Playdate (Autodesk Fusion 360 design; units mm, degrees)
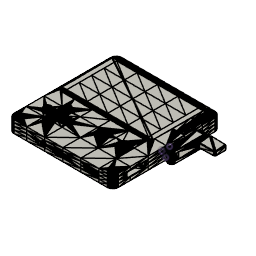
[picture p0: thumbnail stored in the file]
description: Part Number
part number: product0
base_feature "Base Feature1" bodies "Crank wBase", "USB Tab", "Btn Menu", "USB Tab 2", "USB Tab 3", "Cover Mount BR", "Cover Mount BL", "Crank Paddle Hinge"
scale "Scale1" ScaleFactor 1009.706
work_plane "WorkPlane1" AlongDistance 0
work_plane "WorkPlane2" AlongDistance 0
component_from_bodies "Body->Comp"
copy_paste_bodies "CopyPasteBodies1"
move "Move1"
copy_paste_bodies "CopyPasteBodies1"
move "Move1"
copy_paste_bodies "CutPasteBodies1"
copy_paste_bodies "CopyPasteBodies2"
move "Move2"
box_primitive "BoxPrimitive1" DistanceX 27.922 DistanceY 5.467 DistanceZ 5 OffsetDistanceX 0 OffsetDistanceY 0
box_primitive "BoxPrimitive2" DistanceX 27.931 DistanceY 5.556 DistanceZ 6 OffsetDistanceX 0 OffsetDistanceY 0 bodies "Hinge"
box_primitive "BoxPrimitive3" DistanceX 5.517 DistanceY 5.897 DistanceZ 4.5001 OffsetDistanceX 0 OffsetDistanceY 0 bodies "Crank Body"
work_plane "WorkPlane1" AlongDistance 0
sketch "Roll Hinge" plane through (0, 0, -0.4069) normal (0, 0, 1) x axis (1, 0, 0)
  circle C1 centre (44.8638, -16.7129) radius 0.8787
  point P2 (45.5747, -17.2294)
  point P3 (44.1529, -17.2294)
  point P4 (44.5923, -15.8772)
  coincident P2 C1
  coincident P3 C1
  coincident P4 C1
work_axis "WorkAxis1" sketch "Roll Hinge"
work_plane "WorkPlane2" AlongDistance 0
sketch "Tilt Hinge" plane through (40.6438, 0, 0) normal (-1, 0, 0) x axis (0, -1, 0)
  circle C1 centre (16.7129, -4.4318) radius 3.4401
  point P2 (13.9298, -2.4097)
  point P3 (19.496, -2.4097)
  point P4 (16.7129, -7.8718)
  coincident P2 C1
  coincident P3 C1
  coincident P4 C1
work_axis "WorkAxis2" sketch "Tilt Hinge"
move "Move3" RotateAngle 180
copy_paste_bodies "CutPasteBodies1"
copy_paste_bodies "CutPasteBodies1"
extrude "Extrude1" sketch "Roll Hinge" blind 0.1 bodies "ASSY Joint"
extrude "Extrude1" sketch "Roll Hinge" blind -0.1 bodies "ASSY Roll Joint"
joint "Assemble1" alignAngle 0 alignOffsetX 0 alignOffsetY 0 alignOffsetZ 0 RotateMinimum 180 RotateMaximum 360 RotateRest 360
extrude "Extrude1" new body sketch "Tilt Hinge" against normal blind 0.1 bodies "ASSY Tilt Joint"
extrude "Extrude1" new body sketch "Tilt Hinge" along normal blind 0.1 bodies "ASSY Tilt Joint"
joint "Assemble1" alignAngle 0 alignOffsetX 0 alignOffsetY 0 alignOffsetZ 0
as_built_joint "As-built1"
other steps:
base_feature "Base Feature1" bodies "Crank wBase", "*CrankCutPiece"
base_feature "Base Feature1" bodies "Crank Body", "Paddle Screw Facade", "Paddle", "Paddle Base"
base_feature "Base Feature1" bodies "Hinge"
base_feature "Base Feature1" bodies "Crank wBase", "USB Tab", "Cover Mount BR", "Main Body", "Btn Menu", "Screen Glass", "USB Misc 2", "USB Misc"
base_feature "Base Feature2" bodies "Crank Paddle", "Crank Paddle Hinge", "Crank Paddle Base", "Paddle", "Paddle Screw Facade", "Paddle Base"
base_feature "Base Feature3" bodies "Crank wBase (1)", "*HingeCutPiece"
base_feature "Base Feature2" bodies "Crank wBase"
create_component "CreateComponent1"
reparent_decal "ReparentDecal1"
remove_body "RemoveBody1"
create_component "CreateComponent2"
reparent_decal "ReparentDecal2"
remove_body "RemoveBody2"
reparent_decal "ReparentDecal3"
remove_body "RemoveBody3"
reparent_decal "ReparentDecal4"
remove_body "RemoveBody4"
reparent_decal "ReparentDecal5"
remove_body "RemoveBody5"
reparent_decal "ReparentDecal6"
remove_body "RemoveBody6"
reparent_decal "ReparentDecal7"
remove_body "RemoveBody7"
reparent_decal "ReparentDecal8"
remove_body "RemoveBody8"
reparent_decal "ReparentDecal9"
remove_body "RemoveBody9"
reparent_decal "ReparentDecal10"
remove_body "RemoveBody10"
reparent_decal "ReparentDecal11"
remove_body "RemoveBody11"
reparent_decal "ReparentDecal12"
remove_body "RemoveBody12"
reparent_decal "ReparentDecal13"
remove_body "RemoveBody13"
reparent_decal "ReparentDecal14"
remove_body "RemoveBody14"
reparent_decal "ReparentDecal15"
remove_body "RemoveBody15"
reparent_decal "ReparentDecal16"
remove_body "RemoveBody16"
reparent_decal "ReparentDecal17"
remove_body "RemoveBody17"
reparent_decal "ReparentDecal18"
remove_body "RemoveBody18"
reparent_decal "ReparentDecal19"
remove_body "RemoveBody19"
create_component "CreateComponent1"
reparent_decal "ReparentDecal1"
remove_body "RemoveBody1"
reparent_decal "ReparentDecal2"
remove_body "RemoveBody2"
reparent_decal "ReparentDecal3"
remove_body "RemoveBody3"
reparent_decal "ReparentDecal4"
remove_body "RemoveBody4"
create_component "CreateComponent2"
reparent_decal "ReparentDecal5"
remove_body "RemoveBody5"
joint_origin "JointOrigin1"
joint_origin "JointOrigin1"
joint_origin "JointOrigin1"
joint_origin "JointOrigin1"
named bodies: "Crank wBase", "USB Tab", "Btn Menu", "USB Tab 2", "USB Tab 3", "Cover Mount BR", "Cover Mount BL", "Crank Paddle Hinge", "Screen Glass", "Crank Paddle", "Main Body", "Crank Paddle Base", "USB Misc", "USB Misc 2", "USB Misc 3", "Cover Mount TR", "Screen (1)", "BackPlate", "*CrankCutPiece", "Paddle", "Paddle Screw Facade", "Paddle Base", "Crank wBase (1)", "*HingeCutPiece", "Hinge", "Crank Body", "ASSY Joint", "ASSY Roll Joint", "ASSY Tilt Joint"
